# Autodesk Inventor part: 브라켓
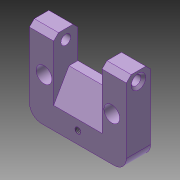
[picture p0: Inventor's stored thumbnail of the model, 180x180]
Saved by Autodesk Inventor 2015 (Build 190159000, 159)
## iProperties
Created: 2023-11
Part Number: 브라켓
Material: 강철, 연강
Document SubType Name: Modeling
Designer: mdu-01
Density: 1 g/cm^3
Appearance: 기본값(1)
Author: mdu-01
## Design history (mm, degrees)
sketch "스케치1"
  geometry: L1 (0, 0)-(0, 10.407); L2 (-20, 5)-(-20, 34); L3 (-20, 34)-(-10, 34); L4 (-10, 34)-(-10, 20); L5 (20, 5)-(20, 34); L6 (20, 34)-(10, 34); L7 (10, 34)-(10, 20); L8 (-15, 0)-(15, 0); L9 (-10, 20)-(10, 20); A1 r 5 centre (-15, 5) between (-20, 5) and (-15, 0); A2 r 5 centre (15, 5) between (15, 0) and (20, 5); 2 further points
  constraints: 18 end point, 4 point on circle, 4 point on line, 4 symmetric about line, 4 tangent, 3 parallel, 2 centre point, 2 perpendicular, 1 equal radius, 1 horizontal alignment, 1 vertical
  dimensions: "d0" = 5 radius of A1; "d1" = 40 distance between parallel lines of L5 L2; "d2" = 34 distance between parallel lines of L3 L8; "d3" = 20 distance between parallel lines of L8 L9; "d4" = 20 distance between parallel lines of L7 L4
extrude "돌출1" new body sketch "스케치1" distance "d5" = 10; taper "d6" = 0 deg
sketch "스케치2"
  geometry: L1 (20, 0)-(20, 10) reference; L2 (34, 10)-(5, 10) reference; L3 (5, 10)-(0, 10) reference; L4 (0, 0)-(0, 10) reference; L5 (5, 0)-(34, 0) reference; L6 (5, 0)-(0, 0) reference; L7 (9, 10)-(20, 3.649)
  constraints: 2 end point, 2 point on line
  dimensions: "d7" = 30 deg angle of L7 L2; "d8" = 9 distance from line of L7.start L4
extrude "돌출2" cut sketch "스케치2" stored distance "d9" = 20; taper "d10" = 0 deg
hole "구멍1" diameter "d13" = 2.459; stored, may be unused: countersink angle "d17" = 90 deg, drill point angle "d19" = 118 deg; dims "d11" = 5, "d12" = 20, "d14" = 6, "d15" = 4, "d16" = 2, "d18" = 8
chamfer "모따기1" distance "d20" = 2; stored, may be unused: second distance "d21" = 2, angle "d22" = 45 deg
hole "구멍2" diameter "d25" = 4; stored, may be unused: countersink angle "d29" = 90 deg, drill point angle "d31" = 118 deg; dims "d23" = 4, "d24" = 5, "d26" = 6, "d27" = 4, "d28" = 2, "d30" = 8
sketch "스케치3"
  geometry: C1 r 1.23 at (-14, 18) reference; C2 r 1.23 at (14, 18) reference; 1 further point
hole "구멍3" sketch "스케치3" at (-14, 18), (14, 18) diameter "d32" = 3.4; stored, may be unused: countersink angle "d36" = 90 deg, drill point angle "d38" = 118 deg; dims "d33" = 6, "d34" = 6.5, "d35" = 6, "d37" = 8
chamfer "모따기2" distance "d39" = 1; stored, may be unused: second distance "d40" = 2, angle "d41" = 45 deg
node "솔리드1"
node "참조1"
node "참조2"
